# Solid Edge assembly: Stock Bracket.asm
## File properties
Author: CADCIM
Template: ansi assembly.asm
Last saved by: Rajat Kamboj
Revision: 9
Application: Solid Edge
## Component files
support_roller_bracket.par
stock_support_roller.par
adjusting_nut_handle.par
adjusting_screw_guide.par
Stock_support_base.par
thrust_bearing.par
adjusting_screw_nut.par
support_adjusting_screw.par
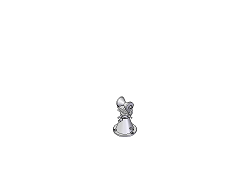
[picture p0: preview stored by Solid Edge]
